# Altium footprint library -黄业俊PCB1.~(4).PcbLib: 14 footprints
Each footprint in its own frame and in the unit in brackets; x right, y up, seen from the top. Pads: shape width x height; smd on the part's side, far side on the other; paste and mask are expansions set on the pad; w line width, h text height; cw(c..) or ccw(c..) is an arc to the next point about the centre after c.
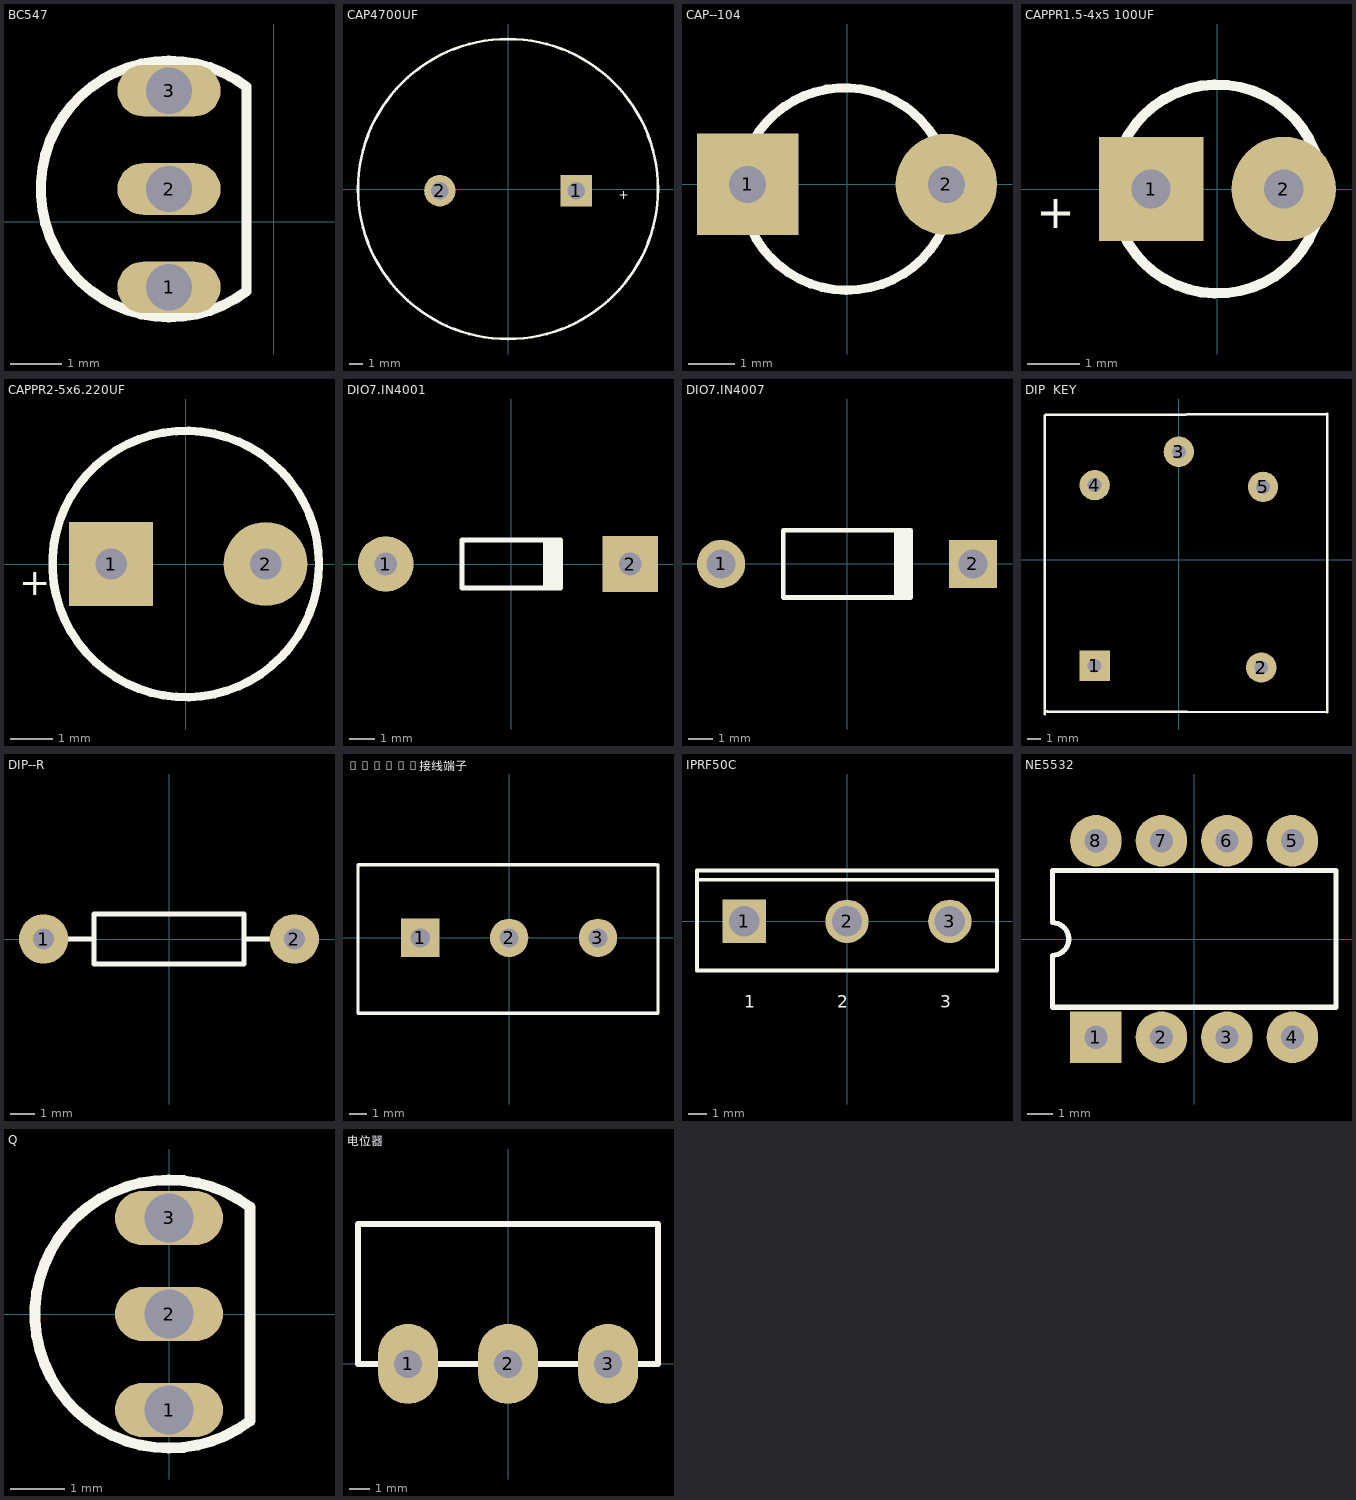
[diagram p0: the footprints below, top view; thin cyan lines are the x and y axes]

## BC547 [mm]
pads (3):
  oval 2x1 hole 0.9: 1(-2.032,-1.27) 2(-2.032,0.635) 3(-2.032,2.54)
Top Overlay:
  lines w0.2: -0.532,-1.345 cw(c-2.032,0.635) -0.532,2.615 -0.532,-1.345

## CAP4700UF [mm]
pads (2):
  rect 2.3x2.3 hole 1.3: 1(5,-0.127)
  round 2.3 hole 1.3: 2(-5,-0.127)
Top Overlay:
  circle w0.2: c0,0 r11
  text "+" at 8.132,-0.737 h0.65

## CAP--104 [mm]
pads (2):
  rect 2.2x2.2 hole 0.8: 1(-2.159,0)
  round 2.2 hole 0.8: 2(2.159,0)
Top Overlay:
  lines w0.2: -2.107,-0.922 ccw(c0,0) 2.092,-0.956 ; -2.043,0.949 cw(c-0.051,-0.201) 2.041,0.756

## CAPPR1.5-4x5 100UF [mm]
pads (2):
  rect 2x2 hole 0.75: 1(-1.27,0)
  round 2 hole 0.75: 2(1.27,0)
Top Overlay:
  circle w0.2: c0,0 r2
  text "+" at -3.475,-0.75 h0.65

## CAPPR2-5x6.220UF [mm]
pads (2):
  rect 2x2 hole 0.75: 1(-1.778,0)
  round 2 hole 0.75: 2(1.905,0)
Top Overlay:
  circle w0.2: c0,0 r3.178
  text "+" at -3.975,-0.75 h0.65

## DIO7.IN4001 [mm]
pads (2):
  round 2.2 hole 0.9: 1(-4.953,0)
  rect 2.2x2.2 hole 0.9: 2(4.699,0)
Top Overlay:
  rectangle: 1.25,-0.95 2.05,0.95
  lines w0.2: 1.95,-0.95 -1.95,-0.95 -1.95,0.95 1.95,0.95

## DIO7.IN4007 [mm]
pads (2):
  round 2 hole 1.2: 1(-5.23,0)
  rect 2x2 hole 1.2: 2(5.23,0)
Top Overlay:
  rectangle: 1.95,-1.404 2.75,1.396
  lines w0.2: 2.65,-1.4 -2.65,-1.4 -2.65,1.4 2.65,1.4

## DIP  KEY [mm]
pads (5):
  rect 2.2x2.2 hole 1: 1(-6.096,-7.683)
  round 2.2 hole 1: 2(5.969,-7.81) 3(0,7.81) 4(-6.096,5.397) 5(6.096,5.271)
Top Overlay:
  lines w0.2: -9.716,-11.176 -9.716,10.424 ; -9.652,10.477 10.752,10.546 10.752,-11.054 -9.525,-10.986

## DIP--R [mm]
pads (2):
  round 2 hole 0.85: 1(-5.08,0) 2(5.08,0)
Top Overlay:
  lines w0.2: -4.064,0 -3.048,0 ; 3.048,0 4.064,0 ; -3.048,-1.016 -3.048,1.016 3.048,1.016 3.048,-1.016 -3.048,-1.016

## HDR1X3接线端子 [mm]
pads (3):
  rect 2.2x2.2 hole 1.1: 1(-5.08,0)
  round 2.2 hole 1.1: 2(0,0) 3(5.08,0)
Top Overlay:
  lines w0.2: 8.382,4.191 -8.636,4.191 -8.636,-4.318 8.509,-4.318 8.509,4.191

## IPRF50C [mm]
pads (3):
  rect 2.3x2.3 hole 1.6: 1(-5.45,0)
  round 2.3 hole 1.6: 2(0,0) 3(5.45,0)
Top Overlay:
  lines w0.2: -7.95,2.2 7.95,2.2 ; -7.95,-2.6 7.95,-2.6 7.95,2.7 -7.95,2.7 -7.95,-2.6
  text "1" at -5.45,-4.575 h0.65
  text "2" at -0.508,-4.575 h0.65
  text "3" at 4.942,-4.575 h0.65

## NE5532 [mm]
pads (8):
  rect 2x2 hole 0.9: 1(-3.81,-3.81)
  round 2 hole 0.9: 2(-1.27,-3.81) 3(1.27,-3.81) 4(3.81,-3.81) 5(3.81,3.81) 6(1.27,3.81) 7(-1.27,3.81) 8(-3.81,3.81)
Top Overlay:
  lines w0.2: -5.5,-2.65 -5.5,-0.635 ccw(c-5.5,0) -5.5,0.635 -5.5,2.65 5.5,2.65 5.5,-2.65 -5.5,-2.65

## Q [mm]
pads (3):
  oval 2x1 hole 0.9: 1(0,-1.778) 2(0,0) 3(0,1.778)
Top Overlay:
  lines w0.2: 1.5,-1.98 cw(c0,0) 1.5,1.98 1.5,-1.98

## 电位器 [mm]
pads (3):
  oval 3x4 hole 1.4: 1(-5,0) 2(0,0) 3(5,0)
Top Overlay:
  lines w0.3: -0.007,6.985 7.493,6.985 7.5,0 0,0 -7.5,0 -7.507,6.985 0.254,6.985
